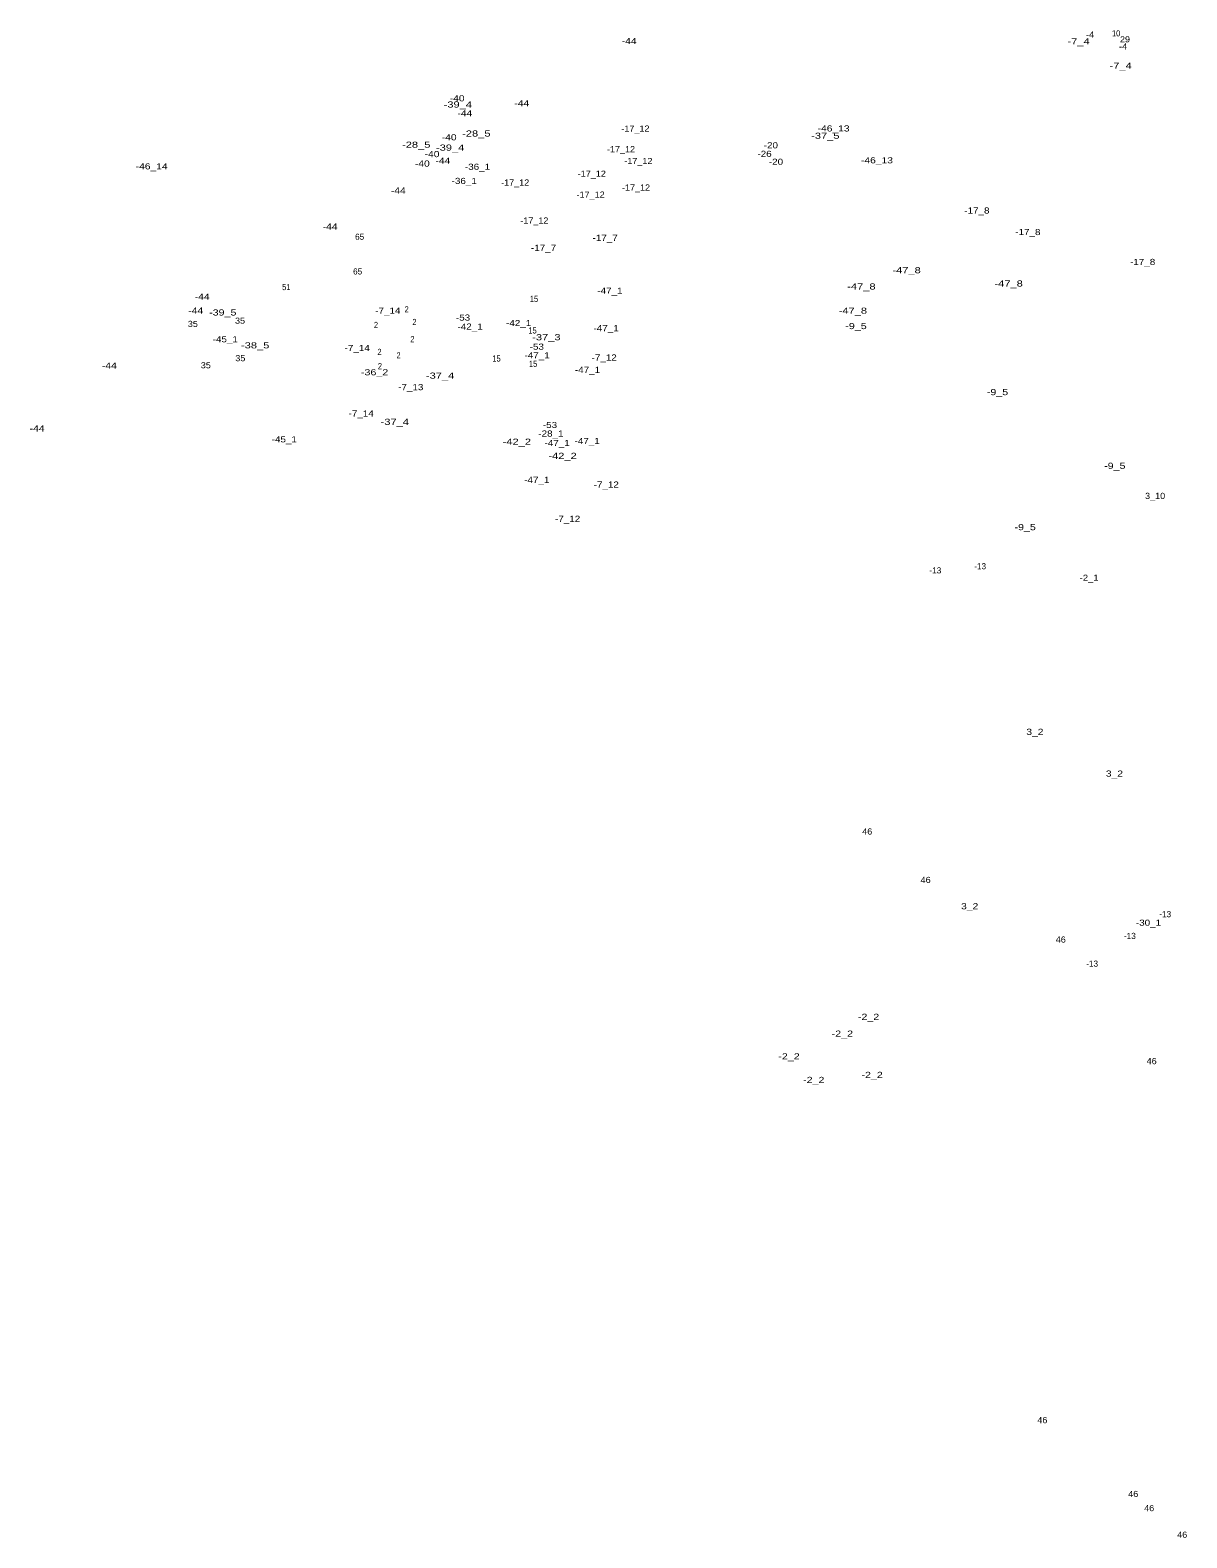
# Model space of a CAD drawing. Extents: x -663241 to -661169, y -1003538 to -1000899.
# Drawn here: x -663241 to -662487, y -1003201 to -1002219 of the extents above; entities that cross this region are included whole.
import ezdxf
from ezdxf.enums import TextEntityAlignment as Align

# ---------------------------------------------------------------- set-up
doc = ezdxf.new("R2010")
doc.units = 0
doc.header["$LTSCALE"] = 1.6
doc.layers.add('24', color=7, linetype='Continuous')

msp = doc.modelspace()

# ---------------------------------------------------------------- texts
at = {"layer": '24'}
for s, width, p in [('-44', 1.25, (-662850.439, -1002227.87)), ('-7_4', 1.35, (-662557.66, -1002228.12)), ('-4', 1.15, (-662550.15, -1002223.64)), ('10', 0.8, (-662533.18, -1002222.85)), ('29', 1.1, (-662527.42, -1002226.77)), ('-4', 1.15, (-662528.64, -1002231.42)), ('-7_4', 1.35, (-662530.199, -1002243.87)), ('-40', 1.25, (-662962.52, -1002265.19)), ('-39_4', 1.35, (-662962.07, -1002269.23)), ('-44', 1.25, (-662957.52, -1002274.98)), ('-44', 1.25, (-662920.41, -1002268.44)), ('-17_12', 1.1, (-662846.37, -1002284.91)), ('-46_13', 1.25, (-662717.26, -1002284.81)), ('-28_5', 1.35, (-662989.179, -1002295.42)), ('-39_4', 1.35, (-662967.07, -1002297.31)), ('-40', 1.25, (-662967.72, -1002290.58)), ('-28_5', 1.35, (-662950.02, -1002288.12)), ('-20', 1.2, (-662758.14, -1002295.78)), ('-37_5', 1.35, (-662722.64, -1002289.56)), ('-40', 1.25, (-662978.86, -1002301.54)), ('-44', 1.25, (-662971.84, -1002305.83)), ('-17_12', 1.1, (-662855.78, -1002298.35)), ('-17_12', 1.1, (-662844.451, -1002306.03)), ('-26', 1.2, (-662762.24, -1002301.36)), ('-20', 1.2, (-662754.78, -1002306.53)), ('-46_13', 1.25, (-662689, -1002305.58)), ('-46_14', 1.25, (-663161.55, -1002309.52)), ('-40', 1.25, (-662985.21, -1002307.69)), ('-36_1', 1.2, (-662949.25, -1002309.78)), ('-17_12', 1.1, (-662874.791, -1002314.29)), ('-44', 1.25, (-663000.86, -1002325.25)), ('-36_1', 1.2, (-662957.9, -1002319.01)), ('-17_12', 1.1, (-662924.711, -1002320.06)), ('-17_12', 1.1, (-662845.99, -1002323.32)), ('-17_12', 1.1, (-662875.561, -1002327.93)), ('-17_12', 1.1, (-662912.231, -1002344.83)), ('-17_8', 1.2, (-662623.9, -1002338.29)), ('-44', 1.25, (-663045.27, -1002348.71)), ('-17_7', 1.2, (-662866.09, -1002356.06)), ('-17_8', 1.2, (-662590.68, -1002352.31)), ('-17_7', 1.2, (-662906.22, -1002362.59)), ('-17_8', 1.2, (-662515.89, -1002371.8)), ('-47_8', 1.35, (-662669.709, -1002377.19)), ('-44', 1.25, (-663128.61, -1002394.41)), ('51', 0.8, (-663073.85, -1002388.16)), ('-47_1', 1.2, (-662862.97, -1002390.53)), ('-47_8', 1.35, (-662699.13, -1002387.77)), ('-47_8', 1.35, (-662603.199, -1002385.84)), ('-44', 1.25, (-663132.829, -1002403.45)), ('-39_5', 1.3, (-663115.22, -1002404.71)), ('-7_14', 1.2, (-663007.67, -1002403.48)), ('2', 0.9, (-662995.419, -1002402.64)), ('15', 0.8, (-662912.459, -1002395.85)), ('-47_8', 1.35, (-662704.699, -1002403.54)), ('35', 1.1, (-663134.73, -1002412.17)), ('35', 1.1, (-663103.97, -1002410.05)), ('2', 0.9, (-663015.41, -1002412.83)), ('2', 0.9, (-662990.319, -1002410.9)), ('-53', 1.2, (-662958.68, -1002408.04)), ('-42_1', 1.2, (-662954.069, -1002413.9)), ('-42_1', 1.2, (-662922.449, -1002411.6)), ('-47_1', 1.2, (-662865.47, -1002414.95)), ('-9_5', 1.3, (-662702.65, -1002413.56)), ('-45_1', 1.2, (-663113.59, -1002422.17)), ('2', 0.9, (-662991.669, -1002422.06)), ('15', 0.8, (-662913.419, -1002416.42)), ('-37_3', 1.35, (-662904.38, -1002420.83)), ('35', 1.1, (-663103.78, -1002434.48)), ('-38_5', 1.35, (-663094.11, -1002426.12)), ('-7_14', 1.2, (-663027.64, -1002427.86)), ('2', 0.9, (-663013.1, -1002430.42)), ('2', 0.9, (-663000.699, -1002432.64)), ('15', 0.8, (-662936.87, -1002434.69)), ('-47_1', 1.2, (-662910.45, -1002432.65)), ('-53', 1.2, (-662910.62, -1002426.98)), ('-7_12', 1.2, (-662866.71, -1002434.04)), ('-44', 1.25, (-663189.09, -1002439.32)), ('35', 1.1, (-663126.27, -1002439.09)), ('-36_2', 1.3, (-663016.32, -1002443.67)), ('2', 0.9, (-663012.819, -1002439.65)), ('15', 0.8, (-662913.03, -1002438.15)), ('-47_1', 1.2, (-662877.58, -1002442.07)), ('-7_13', 1.2, (-662992.73, -1002453.34)), ('-37_4', 1.35, (-662973.63, -1002445.86)), ('-9_5', 1.3, (-662610.48, -1002456.59)), ('-7_14', 1.2, (-663025.05, -1002470.5)), ('-44', 1.25, (-663236.179, -1002480.28)), ('-37_4', 1.35, (-663003.14, -1002475.96)), ('-28_1', 1.2, (-662901.429, -1002483.6)), ('-53', 1.2, (-662902.04, -1002478.01)), ('-45_1', 1.2, (-663075.15, -1002487.36)), ('-42_2', 1.35, (-662923.64, -1002488.89)), ('-47_1', 1.2, (-662897.38, -1002489.77)), ('-47_1', 1.2, (-662877.77, -1002488.42)), ('-42_2', 1.35, (-662893.84, -1002498.12)), ('-9_5', 1.3, (-662534.06, -1002504.61)), ('-47_1', 1.2, (-662910.64, -1002513.79)), ('-7_12', 1.2, (-662865.37, -1002516.83)), ('3_10', 1.1, (-662507.79, -1002524.21)), ('-7_12', 1.2, (-662890.52, -1002539.11)), ('-9_5', 1.3, (-662592.44, -1002544.56)), ('-2_1', 1.15, (-662550.76, -1002577.51)), ('3_2', 1.25, (-662586.11, -1002677.89)), ('3_2', 1.25, (-662534.28, -1002705.12)), ('46', 1.1, (-662695.35, -1002742.84)), ('46', 1.1, (-662657.29, -1002774.38)), ('3_2', 1.25, (-662628.59, -1002791.54)), ('-30_1', 1.2, (-662512.1, -1002802.25)), ('46', 1.1, (-662569.24, -1002813.22)), ('-2_2', 1.3, (-662694.47, -1002863.58)), ('-2_2', 1.3, (-662711.559, -1002874.53)), ('-2_2', 1.3, (-662746.309, -1002889.32)), ('46', 1.1, (-662510.03, -1002892.45)), ('-2_2', 1.3, (-662730.189, -1002904.69)), ('-2_2', 1.3, (-662692.169, -1002901.42)), ('46', 1.1, (-662581.24, -1003126.34)), ('46', 1.1, (-662522.03, -1003174.42)), ('46', 1.1, (-662511.65, -1003183.65)), ('46', 1.1, (-662490.12, -1003200.96))]:
    msp.add_text(s, height=4, dxfattribs=dict(at, width=width)).set_placement(p, align=Align.CENTER)
for s, p in [('65', (-663026.053, -1002355.37)), ('65', (-663027.363, -1002377.96)), ('-13', (-662621.78, -1002570.02)), ('-13', (-662650.961, -1002572.71)), ('-13', (-662501.201, -1002796.67)), ('-13', (-662524.24, -1002810.88)), ('-13', (-662548.811, -1002828.94))]:
    msp.add_text(s, height=4, dxfattribs=at).set_placement(p, align=Align.CENTER)

doc.saveas('drawing.dxf')
